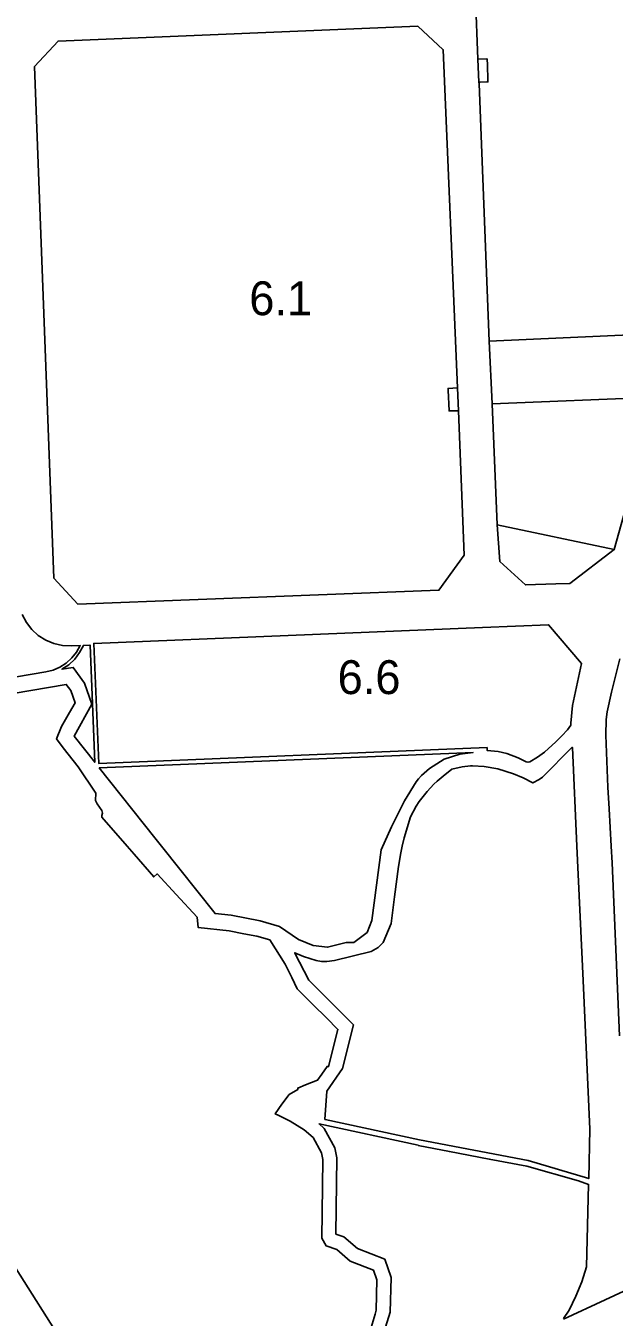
# Model space of a CAD drawing. Extents: x 598968 to 613553, y 4409678 to 4430833.
# Drawn here: x 605532 to 605740.5, y 4415277.9 to 4415735.8 of the extents above; entities that cross this region are included whole.
import ezdxf

# ---------------------------------------------------------------- set-up
doc = ezdxf.new("R2010")
doc.units = 0
for name, color, linetype in [('1', 7, 'Continuous'), ('Sòl Rústic Comú', 7, 'Continuous'), ('Zona 6.1 - ANNEX III E', 7, 'Continuous'), ('Zona 6.2 - ANNEX III E', 7, 'Continuous'), ('Zona 6.6 - ANNEX III E', 7, 'Continuous')]:
    doc.layers.add(name, color=color, linetype=linetype)

msp = doc.modelspace()

# ---------------------------------------------------------------- linework, layer by layer
at = {"layer": '1'}
for points in [[(605755.6368, 4415604.1282), (605740.4921, 4415550.1345), (605724.8042, 4415538.1384), (605719.8961, 4415538.0244), (605719.8921, 4415538.0243), (605709.1157, 4415537.5822), (605709.1118, 4415537.5821), (605700.0553, 4415545.9247), (605699.0619, 4415558.8363), (605699.0578, 4415558.9056), (605699.0218, 4415558.9181), (605697.2621, 4415601.8159), (605696.2849, 4415623.9714), (605693.6167, 4415690.7755), (605692.6376, 4415715.2876), (605692.6147, 4415715.8598), (605692.1748, 4415724.0303), (605692.1742, 4415724.0429), (605691.3339, 4415745.9188)], [(605530.7358, 4415527.1035), (605532.1773, 4415524.3167), (605534.0807, 4415521.8225), (605536.3883, 4415519.6967), (605539.0301, 4415518.004), (605541.9257, 4415516.7956), (605544.9871, 4415516.1085), (605544.991, 4415516.1083), (605548.1233, 4415515.9636), (605551.3125, 4415516.0943), (605550.0028, 4415513.7642), (605548.3341, 4415511.6761), (605546.35, 4415509.8849), (605544.1026, 4415508.4377), (605541.6511, 4415507.3723), (605539.0597, 4415506.7169), (605507.7217, 4415501.4462)], [(605507.7217, 4415501.4462), (605539.0597, 4415506.7169), (605541.6511, 4415507.3723), (605544.1026, 4415508.4377), (605546.35, 4415509.8849), (605548.3341, 4415511.6761), (605550.0028, 4415513.7642), (605551.3125, 4415516.0943), (605548.1233, 4415515.9636), (605544.991, 4415516.1083), (605544.9871, 4415516.1085), (605541.9257, 4415516.7956), (605539.0301, 4415518.004), (605536.3883, 4415519.6967), (605534.0807, 4415521.8225), (605532.1773, 4415524.3167), (605530.7358, 4415527.1035)], [(605742.506, 4415511.3796), (605739.5661, 4415499.5797), (605738.0761, 4415492.6397), (605737.7461, 4415489.8697), (605737.5361, 4415484.3098), (605738.2762, 4415465.85), (605738.7662, 4415458.2401), (605739.4989, 4415444.9561), (605739.8262, 4415439.0203), (605742.4364, 4415377.6909)], [(605742.4364, 4415377.6909), (605739.8262, 4415439.0203), (605739.4989, 4415444.9561), (605738.7662, 4415458.2401), (605738.2762, 4415465.85), (605737.5361, 4415484.3098), (605737.7461, 4415489.8697), (605738.0761, 4415492.6397), (605739.5661, 4415499.5797), (605742.506, 4415511.3796)], [(605508.5911, 4415495.9273), (605546.3376, 4415502.2759), (605547.8888, 4415500.1042), (605549.4244, 4415495.7665), (605547.4793, 4415492.3809), (605544.6139, 4415487.3937), (605542.9042, 4415482.9549), (605545.2728, 4415479.8758), (605545.2747, 4415479.8733), (605550.4892, 4415473.0942), (605556.8151, 4415463.7795), (605556.646, 4415461.1837), (605556.9266, 4415460.669), (605557.2973, 4415459.989), (605558.9711, 4415457.6165), (605559.2158, 4415456.6846), (605558.89, 4415455.7786), (605558.9864, 4415455.2583), (605567.921, 4415444.9531), (605570.3454, 4415442.1568), (605577.3562, 4415434.0707), (605578.5323, 4415435.096), (605585.2747, 4415427.8089), (605592.7639, 4415419.7147), (605593.0852, 4415416.0883), (605604.0236, 4415414.9362), (605609.2776, 4415413.9024), (605613.8215, 4415413.0084), (605618.4809, 4415411.6865), (605623.9611, 4415403.0759), (605626.3219, 4415398.4167), (605628.1835, 4415394.3623), (605633.2952, 4415389.2768), (605633.8406, 4415388.7341), (605633.8827, 4415388.6922), (605638.5407, 4415384.0581), (605642.628, 4415379.9918), (605639.3181, 4415366.8087), (605638.7624, 4415366.8463), (605636.8728, 4415364.1046), (605635.4115, 4415361.9843), (605631.0921, 4415360.2643), (605631.0855, 4415360.2617), (605628.3996, 4415359.1922), (605628.4023, 4415358.6641), (605625.3716, 4415356.9298), (605622.7786, 4415353.4958), (605620.3963, 4415350.0048), (605621.6494, 4415349.4086), (605621.6524, 4415349.4072), (605625.748, 4415347.4586), (605630.6593, 4415344.3599), (605633.793, 4415341.6116), (605636.8586, 4415336.1789), (605637.299, 4415333.8964), (605637.0702, 4415315.0781), (605636.9597, 4415305.9923), (605638.4227, 4415303.2489), (605642.2351, 4415301.9129), (605646.9579, 4415297.8347), (605655.2842, 4415294.5902), (605656.4664, 4415291.1588), (605656.2129, 4415280.4606), (605655.7911, 4415279.0062), (605653.0331, 4415269.498)], [(605653.0331, 4415269.498), (605655.7911, 4415279.0062), (605656.2129, 4415280.4606), (605656.4664, 4415291.1588), (605655.2842, 4415294.5902), (605646.9579, 4415297.8347), (605642.2351, 4415301.9129), (605638.4227, 4415303.2489), (605636.9597, 4415305.9923), (605637.0702, 4415315.0781), (605637.299, 4415333.8964), (605636.8586, 4415336.1789), (605633.793, 4415341.6116), (605630.6593, 4415344.3599), (605625.748, 4415347.4586), (605621.6524, 4415349.4072), (605621.6494, 4415349.4086), (605620.3963, 4415350.0048), (605622.7786, 4415353.4958), (605625.3716, 4415356.9298), (605628.4023, 4415358.6641), (605628.3996, 4415359.1922), (605631.0855, 4415360.2617), (605631.0921, 4415360.2643), (605635.4115, 4415361.9843), (605636.8728, 4415364.1046), (605638.7624, 4415366.8463), (605639.3181, 4415366.8087), (605642.628, 4415379.9918), (605638.5407, 4415384.0581), (605633.8827, 4415388.6922), (605633.8406, 4415388.7341), (605633.2952, 4415389.2768), (605628.1835, 4415394.3623), (605626.3219, 4415398.4167), (605623.9611, 4415403.0759), (605618.4809, 4415411.6865), (605613.8215, 4415413.0084), (605609.2776, 4415413.9024), (605604.0236, 4415414.9362), (605593.0852, 4415416.0883), (605592.7639, 4415419.7147), (605585.2747, 4415427.8089), (605578.5323, 4415435.096), (605577.3562, 4415434.0707), (605570.3454, 4415442.1568), (605567.921, 4415444.9531), (605558.9864, 4415455.2583), (605558.89, 4415455.7786), (605559.2158, 4415456.6846), (605558.9711, 4415457.6165), (605557.2973, 4415459.989), (605556.9266, 4415460.669), (605556.646, 4415461.1837), (605556.8151, 4415463.7795), (605550.4892, 4415473.0942), (605545.2747, 4415479.8733), (605545.2728, 4415479.8758), (605542.9042, 4415482.9549), (605544.6139, 4415487.3937), (605547.4793, 4415492.3809), (605549.4244, 4415495.7665), (605547.8888, 4415500.1042), (605546.3376, 4415502.2759), (605508.5911, 4415495.9273)], [(605649.9412, 4415243.7057), (605661.1567, 4415279.7497), (605661.4474, 4415292.0197), (605659.2185, 4415298.4896), (605649.536, 4415302.2626), (605644.7456, 4415306.3991), (605641.9372, 4415307.3833), (605642.266, 4415334.4257), (605641.5749, 4415338.0079), (605637.6906, 4415344.8912), (605635.9201, 4415346.444), (605635.925, 4415346.4431), (605671.0828, 4415338.8662), (605671.0866, 4415338.8655), (605682.1523, 4415336.6593), (605682.1562, 4415336.6586), (605696.2817, 4415334.0026), (605696.2855, 4415334.0019), (605709.6082, 4415331.5176), (605709.6119, 4415331.5167), (605727.8429, 4415326.2225), (605727.8465, 4415326.2213), (605731.4956, 4415324.994), (605730.7217, 4415295.7798), (605729.0347, 4415290.5228), (605726.9917, 4415285.3938), (605724.6022, 4415280.4167), (605722.5347, 4415277.5027)], [(605722.5347, 4415277.5027), (605724.6022, 4415280.4167), (605726.9917, 4415285.3938), (605729.0347, 4415290.5228), (605730.7217, 4415295.7798), (605731.4956, 4415324.994), (605727.8465, 4415326.2213), (605727.8429, 4415326.2225), (605709.6119, 4415331.5167), (605709.6082, 4415331.5176), (605696.2855, 4415334.0019), (605696.2817, 4415334.0026), (605682.1562, 4415336.6586), (605682.1523, 4415336.6593), (605671.0866, 4415338.8655), (605671.0828, 4415338.8662), (605635.925, 4415346.4431), (605635.9201, 4415346.444), (605637.6906, 4415344.8912), (605641.5749, 4415338.0079), (605642.266, 4415334.4257), (605641.9372, 4415307.3833), (605644.7456, 4415306.3991), (605649.536, 4415302.2626), (605659.2185, 4415298.4896), (605661.4474, 4415292.0197), (605661.1567, 4415279.7497), (605649.9412, 4415243.7057)], [(605525.6972, 4415299.6089), (605547.7802, 4415264.6209)], [(605722.6392, 4415277.2668), (605752.1398, 4415290.8862)]]:
    msp.add_lwpolyline(points, dxfattribs=at)
for points in [[(605679.9744, 4415727.3348), (605685.0491, 4415607.4413), (605685.4091, 4415599.3014), (605687.327, 4415548.0918), (605678.4393, 4415535.722), (605678.4354, 4415535.7219), (605550.4603, 4415530.7699), (605550.4565, 4415530.7698), (605541.9365, 4415539.9596), (605535.058, 4415721.3885), (605543.4009, 4415730.4452), (605543.4049, 4415730.4453), (605670.9139, 4415735.6774), (605670.9178, 4415735.6775)], [(605692.6147, 4415715.8598), (605692.6186, 4415715.8598), (605693.0948, 4415715.875), (605695.4315, 4415715.9489), (605695.7716, 4415715.9597), (605695.7498, 4415716.6542), (605695.5869, 4415721.8318), (605695.5146, 4415724.1304), (605695.4503, 4415724.1285), (605692.485, 4415724.0396), (605692.1787, 4415724.0304), (605692.1748, 4415724.0303)], [(605755.5746, 4415604.1257), (605755.5977, 4415604.2097), (605761.8343, 4415626.9424), (605696.2889, 4415623.9715), (605696.2849, 4415623.9714), (605697.2621, 4415601.8159), (605697.2661, 4415601.816)], [(605685.0358, 4415599.2992), (605685.4051, 4415599.3014), (605685.0451, 4415607.4413), (605681.6451, 4415607.2513), (605681.6699, 4415606.6876), (605681.9952, 4415599.2814)], [(605740.4921, 4415550.1345), (605755.6368, 4415604.1282), (605755.5786, 4415604.1258), (605755.5746, 4415604.1257), (605697.2661, 4415601.816), (605697.2621, 4415601.8159), (605699.0218, 4415558.9181), (605699.0578, 4415558.9056), (605699.0618, 4415558.9047)], [(605740.4921, 4415550.1345), (605699.0618, 4415558.9047), (605699.0578, 4415558.9056), (605699.0619, 4415558.8363), (605700.0553, 4415545.9247), (605709.1118, 4415537.5821), (605709.1157, 4415537.5822), (605719.8921, 4415538.0243), (605719.8961, 4415538.0244), (605724.8042, 4415538.1384)], [(605556.0809, 4415516.8604), (605556.0848, 4415516.8605), (605693.8767, 4415522.5145), (605693.8806, 4415522.5147), (605717.3181, 4415523.4764), (605728.9313, 4415509.7792), (605725.8197, 4415494.838), (605725.1933, 4415488.604), (605725.2257, 4415487.8909), (605723.9528, 4415486.1675), (605721.9555, 4415484.028), (605719.8691, 4415481.9346), (605715.8434, 4415478.2617), (605713.3865, 4415476.4664), (605710.6195, 4415474.8815), (605709.9801, 4415474.6833), (605709.3926, 4415474.8267), (605706.5637, 4415476.2463), (605702.5246, 4415477.7701), (605699.3739, 4415478.46), (605695.53, 4415478.8158), (605695.5006, 4415479.9226), (605557.8317, 4415474.2735), (605557.8278, 4415474.2734)], [(605556.4411, 4415474.7177), (605549.1388, 4415483.9098), (605555.412, 4415495.3053), (605552.7759, 4415502.7518), (605548.7764, 4415508.3508), (605544.8147, 4415507.6849), (605544.8094, 4415507.684), (605547.216, 4415509.2924), (605549.3245, 4415511.2755), (605551.0772, 4415513.5791), (605552.4261, 4415516.1401), (605552.4301, 4415516.1402), (605554.7381, 4415516.2349), (605554.742, 4415516.235), (605556.445, 4415474.7177), (605556.4409, 4415474.7229)], [(605554.742, 4415516.235), (605554.7381, 4415516.2349), (605552.4301, 4415516.1402), (605552.4261, 4415516.1401), (605551.0772, 4415513.5791), (605549.3245, 4415511.2755), (605547.216, 4415509.2924), (605544.8094, 4415507.684), (605544.8147, 4415507.6849), (605548.7764, 4415508.3508), (605552.7759, 4415502.7518), (605555.412, 4415495.3053), (605549.1388, 4415483.9098), (605556.4411, 4415474.7177), (605556.4409, 4415474.7229), (605556.445, 4415474.7177)], [(605638.939, 4415409.1027), (605633.8494, 4415409.7552), (605628.6256, 4415411.8285), (605621.8544, 4415416.5167), (605615.0663, 4415418.4426), (605604.8054, 4415420.4616), (605599.0623, 4415421.0665), (605580.0862, 4415444.9533), (605577.7329, 4415447.9157), (605558.0354, 4415472.7108), (605558.0393, 4415472.7109), (605690.5596, 4415478.1487), (605685.8753, 4415477.6173), (605685.8715, 4415477.6165), (605680.255, 4415475.762), (605675.0558, 4415472.4705), (605672.2146, 4415470.0062), (605671.1857, 4415468.7696), (605670.3799, 4415467.8012), (605666.1903, 4415461.0532), (605661.5974, 4415451.8488), (605658.004, 4415443.6442), (605654.6979, 4415418.5963), (605653.0042, 4415414.3578), (605648.2696, 4415410.7668), (605648.2657, 4415410.7668), (605645.563, 4415410.7793), (605645.5591, 4415410.7793)], [(605653.0042, 4415414.3578), (605654.6979, 4415418.5963), (605658.004, 4415443.6442), (605661.5974, 4415451.8488), (605666.1903, 4415461.0532), (605670.3799, 4415467.8012), (605671.1857, 4415468.7696), (605672.2146, 4415470.0062), (605675.0558, 4415472.4705), (605680.255, 4415475.762), (605685.8715, 4415477.6165), (605685.8753, 4415477.6173), (605690.5596, 4415478.1487), (605558.0393, 4415472.7109), (605558.0354, 4415472.7108), (605577.7329, 4415447.9157), (605580.0862, 4415444.9533), (605599.0623, 4415421.0665), (605604.8054, 4415420.4616), (605615.0663, 4415418.4426), (605621.8544, 4415416.5167), (605628.6256, 4415411.8285), (605633.8494, 4415409.7552), (605638.939, 4415409.1027), (605645.5591, 4415410.7793), (605645.563, 4415410.7793), (605648.2657, 4415410.7668), (605648.2696, 4415410.7668)], [(605725.7117, 4415480.0452), (605725.7168, 4415479.934), (605727.3186, 4415444.9558), (605729.5018, 4415397.28), (605731.9419, 4415344.6005), (605731.552, 4415327.0818), (605710.0761, 4415333.4603), (605671.4964, 4415340.8195), (605638.0504, 4415348.0295), (605638.0067, 4415348.0389), (605638.6867, 4415358.0588), (605644.2466, 4415366.1188), (605648.1279, 4415381.5745), (605648.1365, 4415381.6087), (605632.2765, 4415397.3883), (605627.3586, 4415407.0553), (605627.317, 4415407.1371), (605630.4465, 4415405.8282), (605634.9265, 4415404.4283), (605636.7564, 4415404.0783), (605638.6833, 4415404.0084), (605638.6865, 4415404.0083), (605641.4265, 4415404.4184), (605654.3864, 4415407.5886), (605656.9163, 4415409.0286), (605658.6963, 4415410.8086), (605661.4763, 4415417.5486), (605662.7062, 4415426.9885), (605664.1162, 4415437.7684), (605664.8662, 4415442.6384), (605665.4004, 4415444.9548), (605666.0861, 4415447.9283), (605668.3661, 4415455.2983), (605670.3861, 4415459.1683), (605671.456, 4415460.7883), (605674.216, 4415464.3483), (605676.626, 4415466.9883), (605677.786, 4415467.9883), (605679.9559, 4415469.7683), (605682.9559, 4415472.2284), (605686.6159, 4415473.0484), (605689.6518, 4415473.4302), (605690.3353, 4415473.3912), (605694.4119, 4415473.1587), (605699.2918, 4415472.3286), (605704.8618, 4415470.6088), (605708.2517, 4415469.1388), (605711.7327, 4415467.3695), (605711.7357, 4415467.3689), (605713.9356, 4415468.5689), (605715.0856, 4415469.4089)], [(605725.7168, 4415479.934), (605725.7117, 4415480.0452), (605715.0856, 4415469.4089), (605713.9356, 4415468.5689), (605711.7357, 4415467.3689), (605711.7327, 4415467.3695), (605708.2517, 4415469.1388), (605704.8618, 4415470.6088), (605699.2918, 4415472.3286), (605694.4119, 4415473.1587), (605690.3353, 4415473.3912), (605689.6518, 4415473.4302), (605686.6159, 4415473.0484), (605682.9559, 4415472.2284), (605679.9559, 4415469.7683), (605677.786, 4415467.9883), (605676.626, 4415466.9883), (605674.216, 4415464.3483), (605671.456, 4415460.7883), (605670.3861, 4415459.1683), (605668.3661, 4415455.2983), (605666.0861, 4415447.9283), (605665.4004, 4415444.9548), (605664.8662, 4415442.6384), (605664.1162, 4415437.7684), (605662.7062, 4415426.9885), (605661.4763, 4415417.5486), (605658.6963, 4415410.8086), (605656.9163, 4415409.0286), (605654.3864, 4415407.5886), (605641.4265, 4415404.4184), (605638.6865, 4415404.0083), (605638.6833, 4415404.0084), (605636.7564, 4415404.0783), (605634.9265, 4415404.4283), (605630.4465, 4415405.8282), (605627.317, 4415407.1371), (605627.3586, 4415407.0553), (605632.2765, 4415397.3883), (605648.1365, 4415381.6087), (605648.1279, 4415381.5745), (605644.2466, 4415366.1188), (605638.6867, 4415358.0588), (605638.0067, 4415348.0389), (605638.0504, 4415348.0295), (605671.4964, 4415340.8195), (605710.0761, 4415333.4603), (605731.552, 4415327.0818), (605731.9419, 4415344.6005), (605729.5018, 4415397.28), (605727.3186, 4415444.9558)]]:
    msp.add_lwpolyline(points, close=True, dxfattribs=at)
at = {"layer": 'Sòl Rústic Comú'}
for points in [[(606748.099, 4415756.8444), (606523.4548, 4415650.3535), (606526.3041, 4415644.9028), (606444.3643, 4415606.2638), (605973.5659, 4415384.2565), (605922.3502, 4415361.5323), (605879.4637, 4415341.5373), (605850.355, 4415326.8812), (605825.1238, 4415315.8187), (605810.0857, 4415308.7421), (605797.8641, 4415302.9909), (605797.5694, 4415302.8522), (605793.6554, 4415309.4444), (605793.3719, 4415309.9219), (605752.1398, 4415290.8862), (605722.6392, 4415277.2668)], [(605547.7802, 4415264.6209), (605525.6972, 4415299.6089)]]:
    msp.add_lwpolyline(points, dxfattribs=at)
at = {"layer": 'Zona 6.1 - ANNEX III E'}
for points in [[(605685.0491, 4415607.4413), (605679.9744, 4415727.3348), (605670.9178, 4415735.6775), (605670.9139, 4415735.6774), (605543.4049, 4415730.4453), (605543.4009, 4415730.4452), (605535.058, 4415721.3885), (605541.9365, 4415539.9596), (605550.4565, 4415530.7698), (605550.4603, 4415530.7699), (605678.4354, 4415535.7219), (605678.4393, 4415535.722), (605687.327, 4415548.0918), (605685.4091, 4415599.3014)], [(605685.0358, 4415599.2992), (605681.9952, 4415599.2814), (605681.6699, 4415606.6876), (605681.6451, 4415607.2513), (605685.0451, 4415607.4413), (605685.4051, 4415599.3014)]]:
    msp.add_lwpolyline(points, close=True, dxfattribs=at)
at = {"layer": 'Zona 6.2 - ANNEX III E'}
msp.add_lwpolyline([(605691.3339, 4415745.9188), (605692.1742, 4415724.0429), (605692.1748, 4415724.0303), (605692.1787, 4415724.0304), (605692.485, 4415724.0396), (605695.4503, 4415724.1285), (605695.5146, 4415724.1304), (605695.5869, 4415721.8318), (605695.7498, 4415716.6542), (605695.7716, 4415715.9597), (605695.4315, 4415715.9489), (605693.0948, 4415715.875), (605692.6186, 4415715.8598), (605692.6147, 4415715.8598), (605692.6376, 4415715.2876), (605693.6167, 4415690.7755), (605696.2849, 4415623.9714), (605696.2889, 4415623.9715), (605761.8343, 4415626.9424), (605789.3038, 4415725.3319), (605780.6338, 4415745.7115)], dxfattribs=at)
at = {"layer": 'Zona 6.6 - ANNEX III E'}
msp.add_lwpolyline([(605719.8691, 4415481.9346), (605721.9555, 4415484.028), (605723.9528, 4415486.1675), (605725.2257, 4415487.8909), (605725.1933, 4415488.604), (605725.8197, 4415494.838), (605728.9313, 4415509.7792), (605717.3181, 4415523.4764), (605693.8806, 4415522.5147), (605693.8767, 4415522.5145), (605556.0848, 4415516.8605), (605556.0809, 4415516.8604), (605557.8278, 4415474.2734), (605557.8317, 4415474.2735), (605695.5006, 4415479.9226), (605695.53, 4415478.8158), (605699.3739, 4415478.46), (605702.5246, 4415477.7701), (605706.5637, 4415476.2463), (605709.3926, 4415474.8267), (605709.9801, 4415474.6833), (605710.6195, 4415474.8815), (605713.3865, 4415476.4664), (605715.8434, 4415478.2617)], close=True, dxfattribs=at)

# ---------------------------------------------------------------- texts
at = {"layer": 'Zona 6.1 - ANNEX III E'}
msp.add_text('6.1', height=12, dxfattribs=at).set_placement((605611.1925, 4415633.2237))
at = {"layer": 'Zona 6.6 - ANNEX III E'}
msp.add_text('6.6', height=12, dxfattribs=at).set_placement((605642.5061, 4415498.8749))

doc.saveas('drawing.dxf')
